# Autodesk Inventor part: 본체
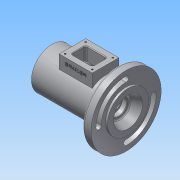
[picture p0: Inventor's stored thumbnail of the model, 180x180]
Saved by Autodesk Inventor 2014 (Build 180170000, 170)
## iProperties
Created: 2017-05
Part Number: 본체
Material: 알루미늄 6061
Document SubType Name: Modeling
Designer: Administrator
Mass: 719.465 g
Surface Area: 636.039 cm^2
Volume: 265.485 cm^3
Density: 2.71 g/cm^3
Appearance: 알루미늄 - 평지
Author: Administrator
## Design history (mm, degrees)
sketch "스케치1"
  geometry: C1 r 31 at (0, 0); 1 further point
  constraints: 1 centre point, 1 coincident
  dimensions: "d0" = 62 diameter of C1
extrude "돌출1" new body sketch "스케치1" stored distance "d1" = 115; taper "d2" = 0 deg
sketch "스케치2" dims "d62" = 50, "d63" = 40, "d65" = 56
  geometry: L1 (57.5, 31)-(57.5, -31) reference; L2 (57.5, -31)-(-57.5, -31) reference; L3 (-57.5, -31)-(-57.5, 31) reference; L4 (-57.5, 31)-(57.5, 31) reference; L5 (-57.5, 0)-(57.5, 0); L6 (-48.5, 0)-(-48.5, 24); L7 (-48.5, 24)-(-45.5, 24); L8 (-45.5, 24)-(-45.5, 20); L9 (-45.5, 20)-(-36.5, 20); L10 (-36.5, 20)-(-36.5, 17.5); L11 (-36.5, 17.5)-(-33.25, 17.5); L12 (-31.5, 17.5)-(-31.5, 18.5); L13 (-31.5, 18.5)-(-33.25, 18.5); L14 (-33.25, 18.5)-(-33.25, 17.5); L15 (-31.5, 17.5)-(-21.5, 17.5); L16 (-20.5, 18.5)-(-20.5, 23); L17 (-17.5, 26)-(14.5, 26); L18 (17.5, 23)-(17.5, 17.5); L19 (17.5, 17.5)-(28.2, 17.5); L20 (28.5, 17.2)-(28.5, 16.5); L21 (28.5, 16.5)-(30.5, 16.5); L22 (33.5, 13.5)-(33.5, 10); L23 (33.5, 10)-(36.2, 10); L24 (36.2, 10)-(36.2, 12.2); L25 (36.5, 12.5)-(42.8, 12.5); L26 (43.5, 12.904)-(43.5, 14.022); L27 (45.318, 16.779)-(57.5, 22); L28 (-21.5, 17.5)-(-20.5, 18.5); L29 (42.8, 12.5)-(43.5, 12.904); A1 r 3 centre (-17.5, 23) between (-17.5, 26) and (-20.5, 23); A2 r 3 centre (14.5, 23) between (17.5, 23) and (14.5, 26); A3 r 0.3 centre (28.2, 17.2) between (28.5, 17.2) and (28.2, 17.5); A4 r 3 centre (30.5, 13.5) between (33.5, 13.5) and (30.5, 16.5); A5 r 0.3 centre (36.5, 12.2) between (36.5, 12.5) and (36.2, 12.2); A6 r 3 centre (46.5, 14.022) between (45.318, 16.779) and (43.5, 14.022); 11 further points
  constraints: 50 end point, 19 parallel, 18 point on line, 12 point on circle, 12 tangent, 6 centre point, 4 midpoint, 2 perpendicular, 1 equal radius, 1 horizontal alignment
  dimensions: "d3" = 48 diameter of L7 L5; "d5" = 12 horizontal distance of L7.end L3.end; "d6" = 3 distance between parallel lines of L8 L6; "d7" = 21 distance between parallel lines of L10 L3; "d9" = 26 distance between parallel lines of L3 L12; "d10" = 1.75 distance between parallel lines of L12 L14; "d11" = 40 diameter of L9 L5; "d12" = 35 diameter of L11 L5; "d13" = 37 diameter of L13 L5; "d14" = 11 distance from line of L16 L12.start; "d15" = 52 diameter of L17 L5; "d16" = 38 distance between parallel lines of L18 L16; "d18" = 35 diameter of L19 L5; "d19" = 11 distance of L18.end point (28.5, 17.5); "d20" = 33 diameter of L21 L5; "d21" = 5 distance of L20.end point (33.5, 16.5); "d22" = 2.7 distance of L22.end L23.end; "d23" = 20 diameter of L23 L5; "d24" = 25 diameter of L25 L5; "d25" = 7.3 distance of point (36.2, 12.5) point (43.5, 12.5); "d26" = 32 diameter of point (43.5, 16) L5; "d27" = 44 diameter of L27.end L5; "d29" = 1 distance of L15.end point (-20.5, 17.5); "d30" = 1 distance of L16.start point (-20.5, 17.5) (= d29); "d31" = 3 radius of A1; "d32" = 0.3 radius of A3; "d33" = 3 radius of A4; "d34" = 0.3 radius of A5; "d35" = 0.7 distance of L25.end point (43.5, 12.5); "d36" = 30 deg angle of L25 L29; "d37" = 3 radius of A6
revolve "회전1" sketch "스케치2" stored, may be unused: angle "d28" = 90 deg
hole "구멍1" diameter "d40" = 40.376; stored, may be unused: countersink angle "d44" = 90 deg, drill point angle "d46" = 0 deg; dims "d38" = 10, "d39" = 10, "d41" = 6, "d42" = 4, "d43" = 2, "d45" = 9
node "작업 평면1"
sketch "스케치4"
  geometry: C1 r 53 at (0, 0); C2 r 20.714 at (0, 0) reference; C3 r 31 at (0, 0) reference; 1 further point
  constraints: 1 centre point, 1 coincident
  dimensions: "d48" = 106 diameter of C1
extrude "돌출2" join sketch "스케치4" distance "d49" = 13; taper "d50" = 0 deg
fillet "모깎기1" dims "d51" = 3
sketch "스케치5"
  geometry: C1 r 31 at (0, 0) reference; C2 r 50 at (0, 0) reference; A1 r 41.5 centre (0, 0) between (0, 41.5) and (-41.5, 0); A2 r 4 centre (0, 41.5) between (0, 37.5) and (0, 45.5); A3 r 4 centre (-41.5, 0) between (-45.5, 0) and (-37.5, 0); A4 r 37.5 centre (0, 0) between (0, 37.5) and (-37.5, 0); A5 r 45.5 centre (0, 0) between (0, 45.5) and (-45.5, 0)
  constraints: 10 point on circle, 5 centre point, 2 coincident, 1 horizontal alignment, 1 tangent, 1 vertical alignment
  dimensions: "d52" = 83 diameter of A1; "d53" = 8 diameter of A2; "d54" = 8 diameter of A3; "d55" = 4 radial gap between concentric circles of A5 A1
extrude "돌출3" cut sketch "스케치5" stored distance "d56" = 13; taper "d57" = 0 deg
node "작업 평면2"
sketch "스케치6"
  geometry: L1 (-23.5, 20)-(26.5, 20); L2 (26.5, 20)-(26.5, -20); L3 (26.5, -20)-(-23.5, -20); L4 (-23.5, -20)-(-23.5, 20); L5 (57.5, -31)-(57.5, 31) reference; L6 (-23.5, 0)-(26.5, 0); L7 (1.5, 20)-(1.5, -20); 1 further point
  constraints: 12 end point, 4 midpoint, 2 parallel, 2 perpendicular, 1 horizontal, 1 horizontal alignment
  dimensions: "d62" = 50 distance of L1.start L1.end; "d63" = 40 distance of L1.end L2.end; "d65" = 56 distance between parallel lines of L5 L7
extrude "돌출4" join sketch "스케치6" stored distance "d66" = 13; taper "d67" = 0 deg
sketch "스케치8"
  geometry: L1 (-23.5, 20)-(26.5, 20) reference; L2 (-23.5, -20)-(-23.5, 20) reference; L3 (26.5, -20)-(-23.5, -20) reference; L4 (26.5, 20)-(26.5, -20) reference; L5 (1.5, 20)-(1.5, -20); L6 (-23.5, 0)-(26.5, 0); L7 (-14.5, -11)-(17.5, -11); L8 (17.5, -11)-(17.5, 11); L9 (17.5, 11)-(-14.5, 11); L10 (-14.5, 11)-(-14.5, -11); L11 (-14.5, -11)-(17.5, 11); L12 (17.5, -11)-(-14.5, 11); 2 further points
  constraints: 16 end point, 7 midpoint, 2 parallel, 1 horizontal, 1 perpendicular
  dimensions: "d68" = 32 distance of L9.end L8.end; "d69" = 22 distance of L8.end L7.end
extrude "돌출5" cut sketch "스케치8" stored distance "d70" = 13; taper "d71" = 0 deg
sketch "스케치9"
  geometry: L1 (-23.5, 20)-(26.5, 20) reference; L2 (-23.5, -20)-(-23.5, 20) reference; L3 (26.5, -20)-(-23.5, -20) reference; L4 (26.5, 20)-(26.5, -20) reference; L5 (1.5, 20)-(1.5, -20); L6 (-23.5, 0)-(26.5, 0); 2 further points
  constraints: 4 end point, 4 midpoint
  dimensions: "d72" = 20.5 distance from line of L5 point (-19, -15.5); "d73" = 15.5 distance from line of point (-19, -15.5) L6
hole "구멍2" sketch "스케치9" at (-19, -15.5) diameter "d74" = 2.459; stored, may be unused: countersink angle "d78" = 90 deg, drill point angle "d80" = 118 deg; dims "d75" = 6, "d76" = 4, "d77" = 2, "d79" = 8
fillet "모깎기3" dims "d88" = 3
fillet "모깎기4" dims "d89" = 1
node "작업 평면3"
sketch "스케치10"
  geometry: L1 (81, 13)-(81, 75) reference; L2 (0, 0)-(50, 0) reference; 3 further points
  constraints: 1 coincident, 1 other
  dimensions: "d91" = 56 distance from line of point (25, 8) L1; "d92" = 8 distance from line of L2 point (25, 8)
feature "엠보싱1" sketch "스케치10" dims "d93" = 0.5, "d94" = 0
node "솔리드1"
pattern_circular "원형 패턴1" dims angle "d59" = 360 deg
pattern_linear "직사각형 패턴1" dims "d83" = 41, "d86" = 31
node "절단 모서리 투영1"
node "절단 모서리 투영2"
other parameters: "d47" = -3, "d61" = 44
